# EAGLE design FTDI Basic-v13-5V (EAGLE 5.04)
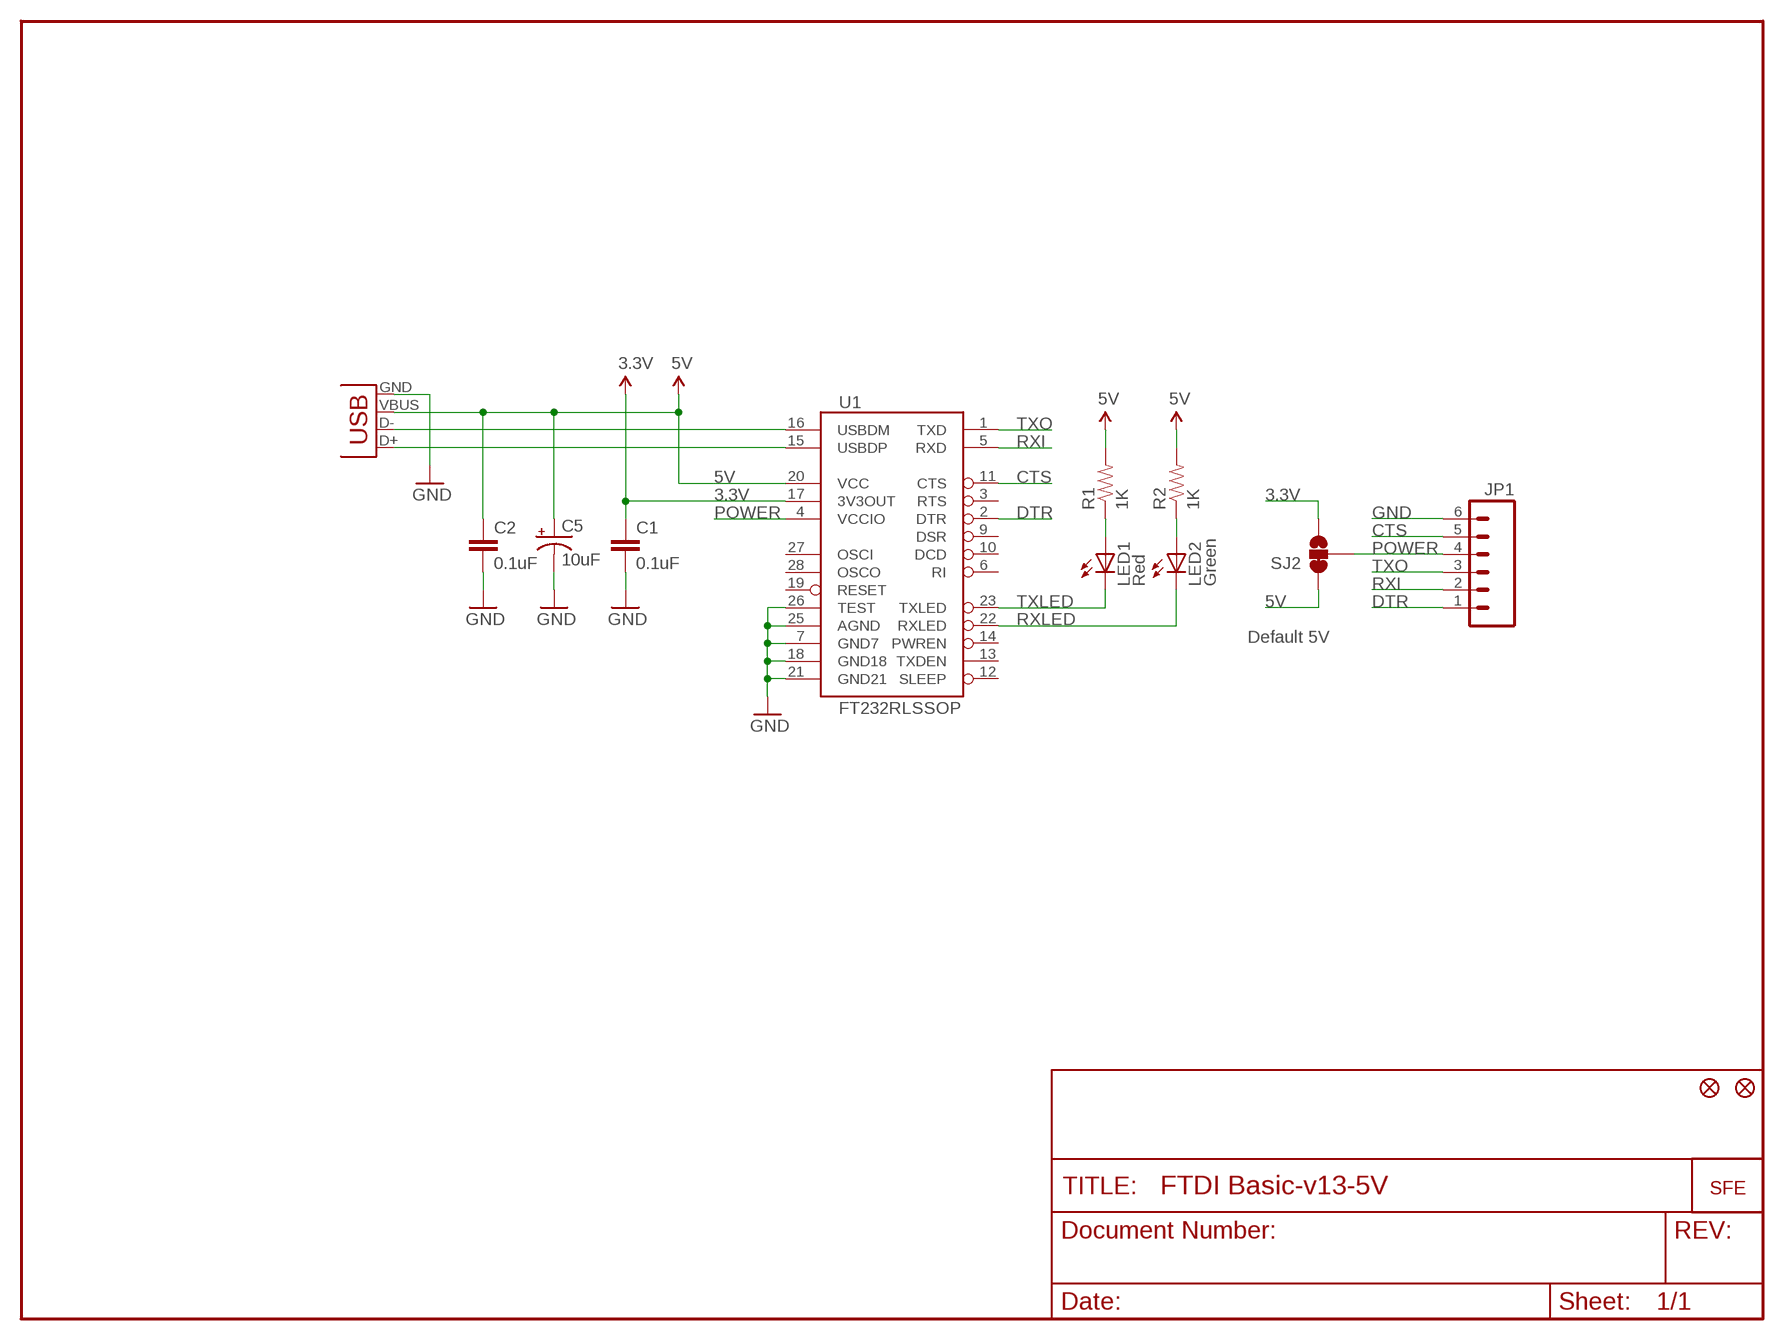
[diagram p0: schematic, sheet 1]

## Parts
C1  0.1uF  CAP0402  [C0402]
C2  0.1uF  CAP0402  [C0402]
C5  10uF  CAP_POL1206  [EIA3216]
JP1  M06SIP  [1X06]
LED1  Red  LED0603  [LED-0603]
LED2  Green  LED0603  [LED-0603]
R1  1K  RESISTOR0402  [C0402]
R2  1K  RESISTOR0402  [C0402]
SJ2  SOLDERJUMPER_2WAYS  [SJ_3]
U1  FT232RLSSOP  [SSOP28DB]
U$2  LOGO-SFENEW  [SFE-NEW-WEBLOGO]
U$6  FIDUCIAL1X2  [FIDUCIAL-1X2]
U$7  FIDUCIAL1X2  [FIDUCIAL-1X2]
X2  USBSMD  [USB-MINIB]

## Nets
3.3V [power]: C1.1 SJ2.3 U1.17(3V3OUT)
5V: C2.1 C5.A(+) R1.2 R2.2 SJ2.1 U1.20(VCC) X2.VBUS
CTS: JP1.5 U1.11(CTS)
DTR: JP1.1 U1.2(DTR)
GND [power]: C1.2 C2.2 C5.C(-) JP1.6 U1.7(GND7) U1.18(GND18) U1.21(GND21) U1.25(AGND) U1.26(TEST) X2.GND
N$1: LED1.A R1.1
N$2: LED2.A R2.1
POWER: JP1.4 SJ2.2 U1.4(VCCIO)
RXI: JP1.2 U1.5(RXD)
RXLED: LED2.C U1.22(RXLED)
TXLED: LED1.C U1.23(TXLED)
TXO: JP1.3 U1.1(TXD)
USB_D+: U1.15(USBDP) X2.D+
USB_D-: U1.16(USBDM) X2.D-
Unconnected: U1.3(RTS) U1.6(RI) U1.9(DSR) U1.10(DCD) U1.12(SLEEP) U1.13(TXDEN) U1.14(PWREN) U1.19(RESET) U1.27(OSCI) U1.28(OSCO)

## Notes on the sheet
- Default 5V

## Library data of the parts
C1 C2 = SparkFun:CAP: Capacitor
C5 = SparkFun:CAP_POL: Capacitor Polarized
JP1 = SparkFun:M06: Header 6 Standard 6-pin 0.1" header. Use with straight break away headers (SKU : PRT-00116), right angle break away headers (PRT-00553), swiss pins (PRT-00743), machine pins (PRT-00117), and female headers (PRT-00115). Molex polarized connector foot print use with SKU : PRT-08094 with associated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
LED1 LED2 = SparkFun:LED: LEDs
R1 R2 = SparkFun:RESISTOR: Resistor
SJ2 = SparkFun:SOLDERJUMPER_2WAY: Solder Jumper 2 way solder jumper
U1 = SparkFun:FT232RL: USB UART FT232RL 4th Generation USB UART (USB <-> Serial) Controller. Spark Fun Electronics SKU : COM-00650
U$2 = SparkFun:LOGO-SFE: Spark Fun Electronics PCB Logo
U$6 U$7 = SparkFun:FIDUCIAL: Fiducial Alignment Points
X2 = SparkFun:USB: USB Connectors USB-B-PTH is fully proven SKU : PRT-00139 USB-miniB is fully proven SKU : PRT-00587 USB-A-PCB is untested. USB-A-H is throughly reviewed, but untested. Spark Fun Electronics SKU : PRT-00437 USB-B-SMT is throughly reviewed, but untested. Needs silkscreen touching up. USB-A-S has not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

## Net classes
0 default: width 0.203 mm
1 power: width 0.254 mm

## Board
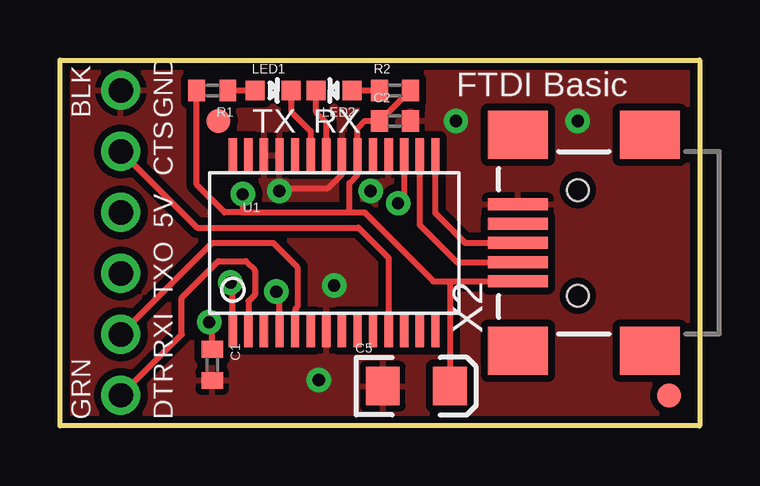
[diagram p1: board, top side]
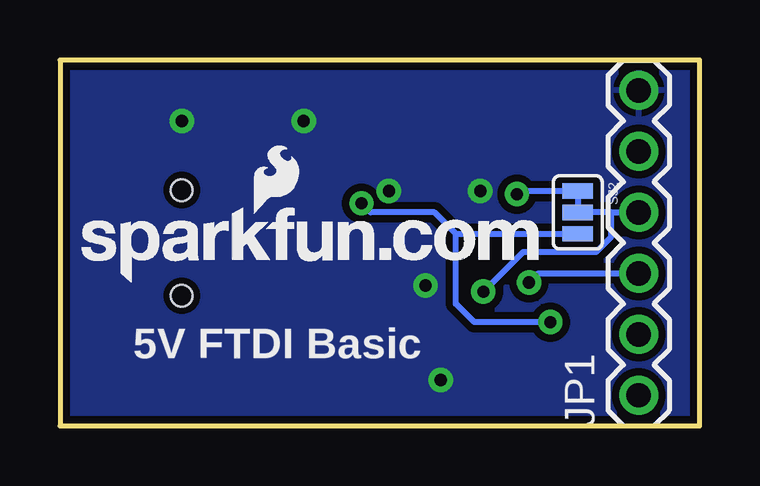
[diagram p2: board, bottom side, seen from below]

Size 26.67 x 15.24 mm. Coordinates in mm from the lower left corner, seen from the top.
Outline: 0,15.24 26.67,15.24 26.67,0 0,0 0,15.24
Copper layers (1*16): Top 0.035mm / dielectric 1.5mm / Bottom 0.035mm
Design rules "SparkFun": minimum track width 8mil, minimum drill 20mil, track to track 8mil, track to pad 8mil, pad to pad 8mil, via to via 8mil, smd to smd 8mil, copper to edge 10mil, drill to drill 8mil, minimum pad ring 12mil, minimum via ring 10mil, stop-mask expansion 4mil, vias tented up to drill 20mil, thermal gap 10mil

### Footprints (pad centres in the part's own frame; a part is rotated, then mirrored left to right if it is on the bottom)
C0402 = smd 0.7 x 0.9: 1 -0.65,0; 2 0.65,0
EIA3216 = smd 1.4 x 1.6: A 1.4,0; C -1.4,0
1X06 = drill 1.016 round: 1 0,0; 2 2.54,0; 3 5.08,0; 4 7.62,0; 5 10.16,0; 6 12.7,0
LED-0603 = smd 0.8 x 0.8: A 0,-0.75; C 0,0.75
SJ_3 = smd 0.635 x 1.27: 1 -0.889,0; 2 0,0; 3 0.889,0
SSOP28DB = smd 0.348 x 1.397: 1 -4.225,-3.656; 2 -3.575,-3.656; 3 -2.925,-3.656; 4 -2.275,-3.656; 5 -1.625,-3.656; 6 -0.975,-3.656; 7 -0.325,-3.656; 8 0.325,-3.656; 9 0.975,-3.656; 10 1.625,-3.656; 11 2.275,-3.656; 12 2.925,-3.656; 13 3.575,-3.656; 14 4.225,-3.656; 15 4.225,3.656; 16 3.575,3.656; 17 2.925,3.656; 18 2.275,3.656; 19 1.625,3.656; 20 0.975,3.656; 21 0.325,3.656; 22 -0.325,3.656; 23 -0.975,3.656; 24 -1.625,3.656; 25 -2.275,3.656; 26 -2.925,3.656; 27 -3.575,3.656; 28 -4.225,3.656
FIDUCIAL-1X2 = smd 1 x 1: 1 0,0
USB-MINIB = smd 2.5 x 0.5: D+ 2.5,0; D- 2.5,0.8; GND 2.5,-1.6; ID 2.5,-0.8; VBUS 2.5,1.6 | smd 2.5 x 2: GND@1 -3,-4.5; GND@2 -3,4.5; GND@3 2.5,4.5; GND@4 2.5,-4.5 | hole 0.9: 0,2.2; 0,-2.2

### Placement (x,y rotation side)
C1  6.35,2.54 270 top
C2  13.97,12.7 0 top
C5  14.86,1.65 0 top
JP1  2.54,1.27 90 bottom
LED1  8.89,13.97 270 top
LED2  11.43,13.97 90 top
R1  6.35,13.97 180 top
R2  13.97,13.97 0 top
SJ2  5.08,8.89 270 bottom
U1  11.43,7.62 0 top
U$2  25.78,5.97 0 bottom
U$6  6.6,12.7 0 top
U$7  25.4,1.27 0 top
X2  21.59,7.62 180 top

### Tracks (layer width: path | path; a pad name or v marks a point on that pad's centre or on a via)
3.3V  (via drill 0.51)
  Top 0.254: C1.1 6.35,4.19 v6.22,4.32 | U1.17 14.36,9.53 v14.1,9.27
  Bottom 0.254: v14.1,9.27 13.72,8.89 11.05,8.89 10.16,8 | v6.22,4.32 9.4,4.32 10.16,5.08 10.16,8 | 10.16,8 SJ2.3
5V  (via drill 0.51)
  Top 0.254: 12.06,8.89 12.7,8.89 15.57,6.02 16.26,6.02 | 12.06,8.89 12.06,10.11 12.4,10.45 U1.20 12.4,12.4 12.7,12.7 C2.1 13.34,12.7 14.61,13.97 R2.2 | 7.62,8.89 6.86,8.89 5.7,10.05 R1.2 | 7.62,8.89 12.06,8.89 | v7.62,9.65 7.62,8.89 | 16.26,6.02 X2.VBUS | C5.A 16.26,6.02
  Bottom 0.254: SJ2.1 7.49,9.78 v7.62,9.65
CTS
  Top 0.254: JP1.5 5.71,8.26 12.45,8.26 13.71,7 U1.11
DTR
  Top 0.254: U1.2 7.86,5.19 8.13,5.46 8.13,6.48 7.75,6.86 6.6,6.86 5.08,5.33 5.08,3.81 JP1.1
GND  (via drill 0.51)
  Top 0.254: U1.21 11.76,10.48 11.18,9.91 9.27,9.91 v9.14,9.78
  other vias: 12.95,9.78 21.59,12.7 16.51,12.7 10.79,1.91 11.43,5.84
  pour Bottom (isolate 0.305): 0,0 0,15.24 26.67,15.24 26.67,0
  pour Top (isolate 0.305): 0,0 0,15.24 26.67,15.24 26.67,0
N$1
  Top 0.254: 6.99,13.97 R1.1 LED1.A
N$2
  Top 0.254: 13.32,13.86 13.34,13.84 | 13.32,13.86 R2.1 | LED2.A 13.21,13.97 13.32,13.86
N$3
  Bottom 0.254: 5.08,9.78 5.08,8.89
POWER  (via drill 0.51)
  Top 0.254: U1.4 9.14,5.46 v9.02,5.59
  Bottom 0.254: v9.02,5.59 7.37,7.24 4.32,7.24 3.68,7.87 3.68,8.89 | 3.68,8.89 JP1.4 | 3.68,8.89 SJ2.2
RXI
  Top 0.254: JP1.2 6.35,7.62 8.89,7.62 9.91,6.6 9.91,4.95 9.8,4.85 U1.5
RXLED
  Top 0.254: U1.22 11.11,12.64 10.68,13.07 LED2.C
TXLED
  Top 0.254: U1.23 10.46,12.28 9.64,13.09 LED1.C
TXO  (via drill 0.51)
  Top 0.254: U1.1 7.21,5.88 v7.11,5.97
  Bottom 0.254: JP1.3 6.73,6.35 v7.11,5.97
USB_D+
  Top 0.254: X2.D+ 16.89,7.62 15.65,8.86 U1.15
USB_D-
  Top 0.254: X2.D- 16.55,6.82 15.01,8.36 U1.16

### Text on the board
tPlace: FTDI Basic | BLK | GND | TX | RX | CTS | 5V | TXO | RXI | GRN | DTR
bPlace: 5V FTDI Basic
tValues: Close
